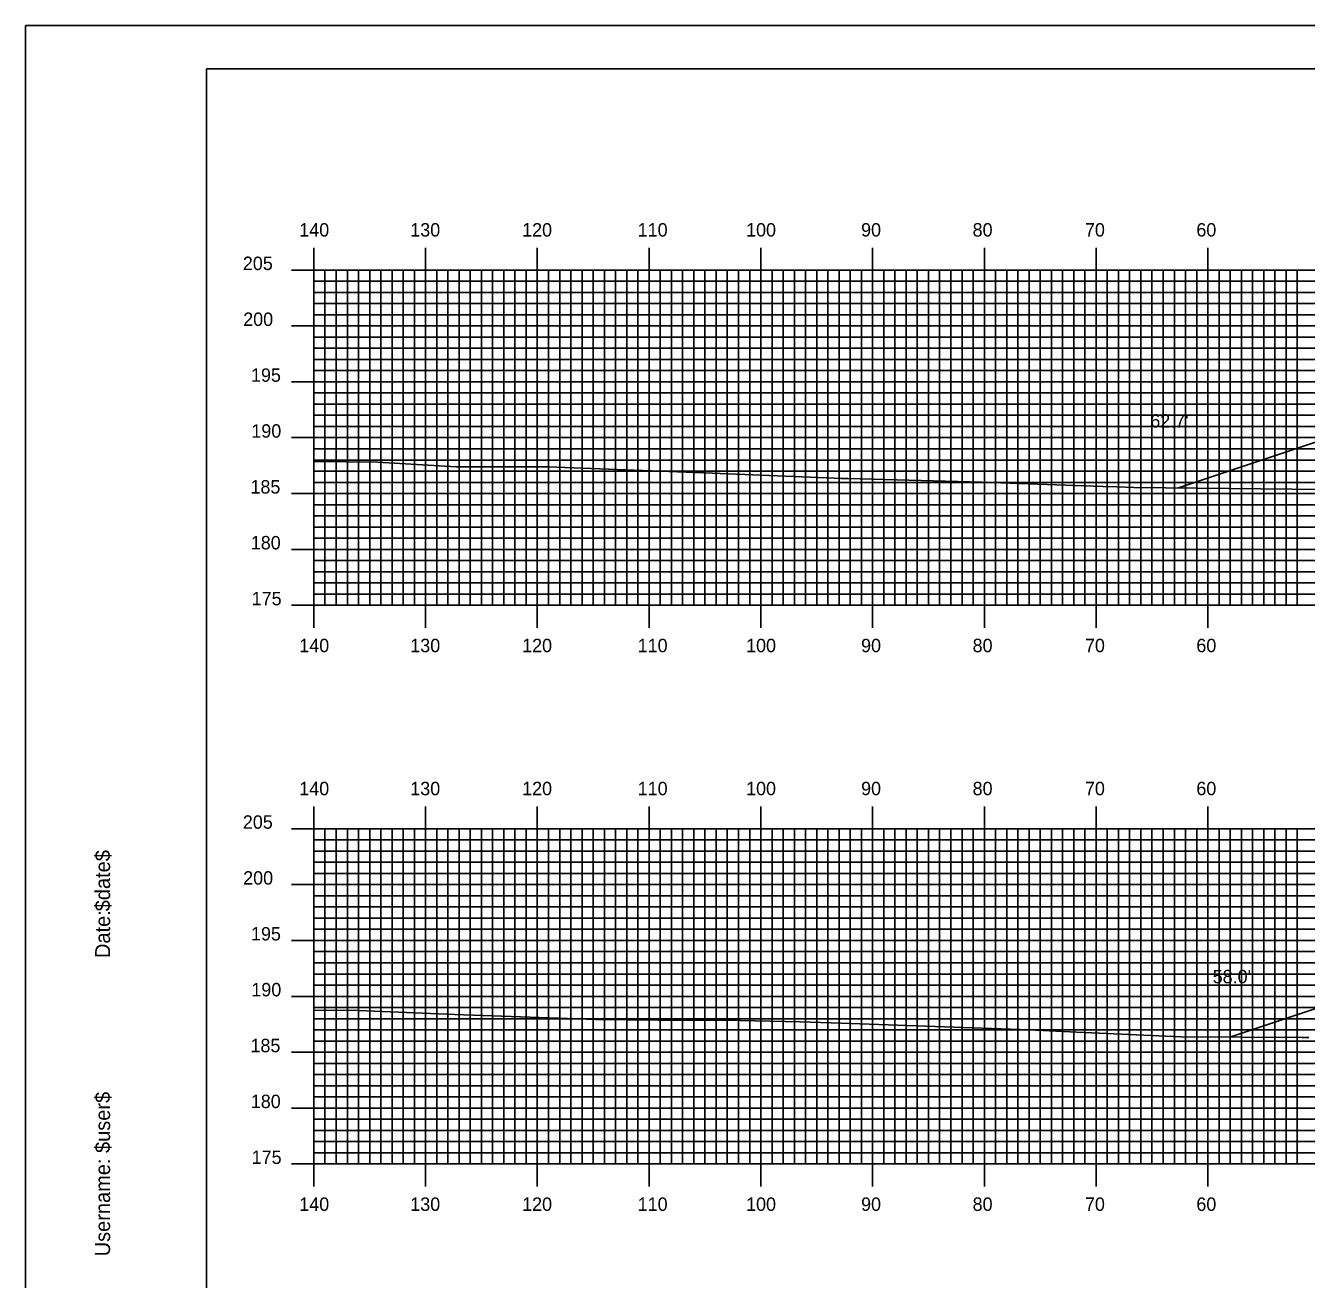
# Model space of a CAD drawing. Extents: x 1808226 to 1808569, y 442591 to 442811.
# Drawn here: x 1808225.5 to 1808340.1, y 442698.3 to 442810.5 of the extents above; entities that cross this region are included whole.
import ezdxf

# ---------------------------------------------------------------- set-up
doc = ezdxf.new("R2010")
doc.units = 0
for name, color, linetype in [('BORDER', 7, 'Continuous'), ('D_Roadway_Centerline', 7, 'Continuous'), ('D_Roadway_SlopeLines', 7, 'Continuous'), ('D_Text_Standard', 7, 'Continuous'), ('H_V ANNOTATION', 7, 'Continuous'), ('MAJOR', 7, 'Continuous'), ('MINOR', 7, 'Continuous'), ('PLOT BOUNDARY', 7, 'Continuous'), ('S_Roadway_Centerline', 7, 'Continuous')]:
    doc.layers.add(name, color=color, linetype=linetype)

msp = doc.modelspace()

# ---------------------------------------------------------------- linework, layer by layer
at = {"layer": 'BORDER'}
msp.add_lwpolyline([(1808241.7, 442596.67), (1808561.7, 442596.67), (1808561.7, 442806.67), (1808241.7, 442806.67)], close=True, dxfattribs=at)
at = {"layer": 'D_Roadway_Centerline'}
for points in [[(1808328.57, 442769.16), (1808357.86, 442778.92), (1808359.81, 442779.41), (1808369.86, 442781.92), (1808379.3, 442782.3), (1808391.3, 442782.54), (1808403.3, 442782.3), (1808411.3, 442781.98), (1808414.3, 442781.86), (1808421.57, 442779.44), (1808456.46, 442767.81)], [(1808333.28, 442720.03), (1808359.3, 442728.7), (1808361.12, 442729.16), (1808371.3, 442731.7), (1808379.3, 442732.02), (1808391.3, 442732.26), (1808403.3, 442732.02), (1808411.3, 442731.7), (1808414.3, 442731.58), (1808421.57, 442729.16), (1808455.49, 442717.85)]]:
    msp.add_lwpolyline(points, dxfattribs=at)
at = {"layer": 'D_Roadway_SlopeLines'}
for points in [[(1808369.86, 442781.92), (1808357.86, 442778.92), (1808328.57, 442769.16)], [(1808371.3, 442731.7), (1808359.3, 442728.7), (1808333.28, 442720.03)]]:
    msp.add_lwpolyline(points, dxfattribs=at)
at = {"layer": 'MAJOR'}
for p, q in [((1808251.3, 442790.67), (1808251.3, 442788.67)), ((1808261.3, 442790.67), (1808261.3, 442788.67)), ((1808271.3, 442790.67), (1808271.3, 442788.67)), ((1808281.3, 442790.67), (1808281.3, 442788.67)), ((1808291.3, 442790.67), (1808291.3, 442788.67)), ((1808301.3, 442790.67), (1808301.3, 442788.67)), ((1808311.3, 442790.67), (1808311.3, 442788.67)), ((1808321.3, 442790.67), (1808321.3, 442788.67)), ((1808331.3, 442790.67), (1808331.3, 442788.67)), ((1808249.29, 442788.67), (1808251.3, 442788.67)), ((1808251.3, 442788.67), (1808531.3, 442788.67)), ((1808251.3, 442758.67), (1808251.3, 442788.67)), ((1808251.3, 442758.67), (1808251.3, 442788.67)), ((1808251.3, 442788.67), (1808531.3, 442788.67)), ((1808261.3, 442758.67), (1808261.3, 442788.67)), ((1808271.3, 442758.67), (1808271.3, 442788.67)), ((1808281.3, 442758.67), (1808281.3, 442788.67)), ((1808291.3, 442758.67), (1808291.3, 442788.67)), ((1808301.3, 442758.67), (1808301.3, 442788.67)), ((1808311.3, 442758.67), (1808311.3, 442788.67)), ((1808321.3, 442758.67), (1808321.3, 442788.67)), ((1808331.3, 442758.67), (1808331.3, 442788.67)), ((1808249.29, 442783.67), (1808251.3, 442783.67)), ((1808251.3, 442783.67), (1808531.3, 442783.67)), ((1808249.29, 442778.67), (1808251.3, 442778.67)), ((1808251.3, 442778.67), (1808531.3, 442778.67)), ((1808249.29, 442773.67), (1808251.3, 442773.67)), ((1808251.3, 442773.67), (1808531.3, 442773.67)), ((1808249.29, 442768.67), (1808251.3, 442768.67)), ((1808251.3, 442768.67), (1808531.3, 442768.67)), ((1808249.29, 442763.67), (1808251.3, 442763.67)), ((1808251.3, 442763.67), (1808531.3, 442763.67)), ((1808249.29, 442758.67), (1808251.3, 442758.67)), ((1808251.3, 442758.67), (1808531.3, 442758.67)), ((1808251.3, 442758.67), (1808531.3, 442758.67)), ((1808251.3, 442756.66), (1808251.3, 442758.67)), ((1808261.3, 442756.66), (1808261.3, 442758.67)), ((1808271.3, 442756.66), (1808271.3, 442758.67)), ((1808281.3, 442756.66), (1808281.3, 442758.67)), ((1808291.3, 442756.66), (1808291.3, 442758.67)), ((1808301.3, 442756.66), (1808301.3, 442758.67)), ((1808311.3, 442756.66), (1808311.3, 442758.67)), ((1808321.3, 442756.66), (1808321.3, 442758.67)), ((1808331.3, 442756.66), (1808331.3, 442758.67)), ((1808251.3, 442740.67), (1808251.3, 442738.67)), ((1808261.3, 442740.67), (1808261.3, 442738.67)), ((1808271.3, 442740.67), (1808271.3, 442738.67)), ((1808281.3, 442740.67), (1808281.3, 442738.67)), ((1808291.3, 442740.67), (1808291.3, 442738.67)), ((1808301.3, 442740.67), (1808301.3, 442738.67)), ((1808311.3, 442740.67), (1808311.3, 442738.67)), ((1808321.3, 442740.67), (1808321.3, 442738.67)), ((1808331.3, 442740.67), (1808331.3, 442738.67)), ((1808249.29, 442738.67), (1808251.3, 442738.67)), ((1808251.3, 442738.67), (1808531.3, 442738.67)), ((1808251.3, 442708.67), (1808251.3, 442738.67)), ((1808251.3, 442708.67), (1808251.3, 442738.67)), ((1808251.3, 442738.67), (1808531.3, 442738.67)), ((1808261.3, 442708.67), (1808261.3, 442738.67)), ((1808271.3, 442708.67), (1808271.3, 442738.67)), ((1808281.3, 442708.67), (1808281.3, 442738.67)), ((1808291.3, 442708.67), (1808291.3, 442738.67)), ((1808301.3, 442708.67), (1808301.3, 442738.67)), ((1808311.3, 442708.67), (1808311.3, 442738.67)), ((1808321.3, 442708.67), (1808321.3, 442738.67)), ((1808331.3, 442708.67), (1808331.3, 442738.67)), ((1808249.29, 442733.67), (1808251.3, 442733.67)), ((1808251.3, 442733.67), (1808531.3, 442733.67)), ((1808249.29, 442728.67), (1808251.3, 442728.67)), ((1808251.3, 442728.67), (1808531.3, 442728.67)), ((1808249.29, 442723.67), (1808251.3, 442723.67)), ((1808251.3, 442723.67), (1808531.3, 442723.67)), ((1808249.29, 442718.67), (1808251.3, 442718.67)), ((1808251.3, 442718.67), (1808531.3, 442718.67)), ((1808249.29, 442713.67), (1808251.3, 442713.67)), ((1808251.3, 442713.67), (1808531.3, 442713.67)), ((1808249.29, 442708.67), (1808251.3, 442708.67)), ((1808251.3, 442708.67), (1808531.3, 442708.67)), ((1808251.3, 442708.67), (1808531.3, 442708.67)), ((1808251.3, 442706.66), (1808251.3, 442708.67)), ((1808261.3, 442706.66), (1808261.3, 442708.67)), ((1808271.3, 442706.66), (1808271.3, 442708.67)), ((1808281.3, 442706.66), (1808281.3, 442708.67)), ((1808291.3, 442706.66), (1808291.3, 442708.67)), ((1808301.3, 442706.66), (1808301.3, 442708.67)), ((1808311.3, 442706.66), (1808311.3, 442708.67)), ((1808321.3, 442706.66), (1808321.3, 442708.67)), ((1808331.3, 442706.66), (1808331.3, 442708.67))]:
    msp.add_line(p, q, dxfattribs=at)
at = {"layer": 'MINOR'}
for p, q in [((1808252.3, 442758.67), (1808252.3, 442788.67)), ((1808253.3, 442758.67), (1808253.3, 442788.67)), ((1808254.3, 442758.67), (1808254.3, 442788.67)), ((1808255.3, 442758.67), (1808255.3, 442788.67)), ((1808256.3, 442758.67), (1808256.3, 442788.67)), ((1808257.3, 442758.67), (1808257.3, 442788.67)), ((1808258.3, 442758.67), (1808258.3, 442788.67)), ((1808259.3, 442758.67), (1808259.3, 442788.67)), ((1808260.3, 442758.67), (1808260.3, 442788.67)), ((1808262.3, 442758.67), (1808262.3, 442788.67)), ((1808263.3, 442758.67), (1808263.3, 442788.67)), ((1808264.3, 442758.67), (1808264.3, 442788.67)), ((1808265.3, 442758.67), (1808265.3, 442788.67)), ((1808266.3, 442758.67), (1808266.3, 442788.67)), ((1808267.3, 442758.67), (1808267.3, 442788.67)), ((1808268.3, 442758.67), (1808268.3, 442788.67)), ((1808269.3, 442758.67), (1808269.3, 442788.67)), ((1808270.3, 442758.67), (1808270.3, 442788.67)), ((1808272.3, 442758.67), (1808272.3, 442788.67)), ((1808273.3, 442758.67), (1808273.3, 442788.67)), ((1808274.3, 442758.67), (1808274.3, 442788.67)), ((1808275.3, 442758.67), (1808275.3, 442788.67)), ((1808276.3, 442758.67), (1808276.3, 442788.67)), ((1808277.3, 442758.67), (1808277.3, 442788.67)), ((1808278.3, 442758.67), (1808278.3, 442788.67)), ((1808279.3, 442758.67), (1808279.3, 442788.67)), ((1808280.3, 442758.67), (1808280.3, 442788.67)), ((1808282.3, 442758.67), (1808282.3, 442788.67)), ((1808283.3, 442758.67), (1808283.3, 442788.67)), ((1808284.3, 442758.67), (1808284.3, 442788.67)), ((1808285.3, 442758.67), (1808285.3, 442788.67)), ((1808286.3, 442758.67), (1808286.3, 442788.67)), ((1808287.3, 442758.67), (1808287.3, 442788.67)), ((1808288.3, 442758.67), (1808288.3, 442788.67)), ((1808289.3, 442758.67), (1808289.3, 442788.67)), ((1808290.3, 442758.67), (1808290.3, 442788.67)), ((1808292.3, 442758.67), (1808292.3, 442788.67)), ((1808293.3, 442758.67), (1808293.3, 442788.67)), ((1808294.3, 442758.67), (1808294.3, 442788.67)), ((1808295.3, 442758.67), (1808295.3, 442788.67)), ((1808296.3, 442758.67), (1808296.3, 442788.67)), ((1808297.3, 442758.67), (1808297.3, 442788.67)), ((1808298.3, 442758.67), (1808298.3, 442788.67)), ((1808299.3, 442758.67), (1808299.3, 442788.67)), ((1808300.3, 442758.67), (1808300.3, 442788.67)), ((1808302.3, 442758.67), (1808302.3, 442788.67)), ((1808303.3, 442758.67), (1808303.3, 442788.67)), ((1808304.3, 442758.67), (1808304.3, 442788.67)), ((1808305.3, 442758.67), (1808305.3, 442788.67)), ((1808306.3, 442758.67), (1808306.3, 442788.67)), ((1808307.3, 442758.67), (1808307.3, 442788.67)), ((1808308.3, 442758.67), (1808308.3, 442788.67)), ((1808309.3, 442758.67), (1808309.3, 442788.67)), ((1808310.3, 442758.67), (1808310.3, 442788.67)), ((1808312.3, 442758.67), (1808312.3, 442788.67)), ((1808313.3, 442758.67), (1808313.3, 442788.67)), ((1808314.3, 442758.67), (1808314.3, 442788.67)), ((1808315.3, 442758.67), (1808315.3, 442788.67)), ((1808316.3, 442758.67), (1808316.3, 442788.67)), ((1808317.3, 442758.67), (1808317.3, 442788.67)), ((1808318.3, 442758.67), (1808318.3, 442788.67)), ((1808319.3, 442758.67), (1808319.3, 442788.67)), ((1808320.3, 442758.67), (1808320.3, 442788.67)), ((1808322.3, 442758.67), (1808322.3, 442788.67)), ((1808323.3, 442758.67), (1808323.3, 442788.67)), ((1808324.3, 442758.67), (1808324.3, 442788.67)), ((1808325.3, 442758.67), (1808325.3, 442788.67)), ((1808326.3, 442758.67), (1808326.3, 442788.67)), ((1808327.3, 442758.67), (1808327.3, 442788.67)), ((1808328.3, 442758.67), (1808328.3, 442788.67)), ((1808329.3, 442758.67), (1808329.3, 442788.67)), ((1808330.3, 442758.67), (1808330.3, 442788.67)), ((1808332.3, 442758.67), (1808332.3, 442788.67)), ((1808333.3, 442758.67), (1808333.3, 442788.67)), ((1808334.3, 442758.67), (1808334.3, 442788.67)), ((1808335.3, 442758.67), (1808335.3, 442788.67)), ((1808336.3, 442758.67), (1808336.3, 442788.67)), ((1808337.3, 442758.67), (1808337.3, 442788.67)), ((1808338.3, 442758.67), (1808338.3, 442788.67)), ((1808339.3, 442758.67), (1808339.3, 442788.67)), ((1808251.3, 442787.67), (1808531.3, 442787.67)), ((1808251.3, 442787.67), (1808253.3, 442787.67)), ((1808251.3, 442786.67), (1808531.3, 442786.67)), ((1808251.3, 442786.67), (1808253.3, 442786.67)), ((1808251.3, 442785.67), (1808531.3, 442785.67)), ((1808251.3, 442785.67), (1808253.3, 442785.67)), ((1808251.3, 442784.67), (1808531.3, 442784.67)), ((1808251.3, 442784.67), (1808253.3, 442784.67)), ((1808251.3, 442782.67), (1808531.3, 442782.67)), ((1808251.3, 442782.67), (1808253.3, 442782.67)), ((1808251.3, 442781.67), (1808531.3, 442781.67)), ((1808251.3, 442781.67), (1808253.3, 442781.67)), ((1808251.3, 442780.67), (1808531.3, 442780.67)), ((1808251.3, 442780.67), (1808253.3, 442780.67)), ((1808251.3, 442779.67), (1808531.3, 442779.67)), ((1808251.3, 442779.67), (1808253.3, 442779.67)), ((1808251.3, 442777.67), (1808531.3, 442777.67)), ((1808251.3, 442777.67), (1808253.3, 442777.67)), ((1808251.3, 442776.67), (1808531.3, 442776.67)), ((1808251.3, 442776.67), (1808253.3, 442776.67)), ((1808251.3, 442775.67), (1808531.3, 442775.67)), ((1808251.3, 442775.67), (1808253.3, 442775.67)), ((1808251.3, 442774.67), (1808531.3, 442774.67)), ((1808251.3, 442774.67), (1808253.3, 442774.67)), ((1808251.3, 442772.67), (1808531.3, 442772.67)), ((1808251.3, 442772.67), (1808253.3, 442772.67)), ((1808251.3, 442771.67), (1808531.3, 442771.67)), ((1808251.3, 442771.67), (1808253.3, 442771.67)), ((1808251.3, 442770.67), (1808531.3, 442770.67)), ((1808251.3, 442770.67), (1808253.3, 442770.67)), ((1808251.3, 442769.67), (1808531.3, 442769.67)), ((1808251.3, 442769.67), (1808253.3, 442769.67)), ((1808251.3, 442767.67), (1808531.3, 442767.67)), ((1808251.3, 442767.67), (1808253.3, 442767.67)), ((1808251.3, 442766.67), (1808531.3, 442766.67)), ((1808251.3, 442766.67), (1808253.3, 442766.67)), ((1808251.3, 442765.67), (1808531.3, 442765.67)), ((1808251.3, 442765.67), (1808253.3, 442765.67)), ((1808251.3, 442764.67), (1808531.3, 442764.67)), ((1808251.3, 442764.67), (1808253.3, 442764.67)), ((1808251.3, 442762.67), (1808531.3, 442762.67)), ((1808251.3, 442762.67), (1808253.3, 442762.67)), ((1808251.3, 442761.67), (1808531.3, 442761.67)), ((1808251.3, 442761.67), (1808253.3, 442761.67)), ((1808251.3, 442760.67), (1808531.3, 442760.67)), ((1808251.3, 442760.67), (1808253.3, 442760.67)), ((1808251.3, 442759.67), (1808531.3, 442759.67)), ((1808251.3, 442759.67), (1808253.3, 442759.67)), ((1808252.3, 442708.67), (1808252.3, 442738.67)), ((1808253.3, 442708.67), (1808253.3, 442738.67)), ((1808254.3, 442708.67), (1808254.3, 442738.67)), ((1808255.3, 442708.67), (1808255.3, 442738.67)), ((1808256.3, 442708.67), (1808256.3, 442738.67)), ((1808257.3, 442708.67), (1808257.3, 442738.67)), ((1808258.3, 442708.67), (1808258.3, 442738.67)), ((1808259.3, 442708.67), (1808259.3, 442738.67)), ((1808260.3, 442708.67), (1808260.3, 442738.67)), ((1808262.3, 442708.67), (1808262.3, 442738.67)), ((1808263.3, 442708.67), (1808263.3, 442738.67)), ((1808264.3, 442708.67), (1808264.3, 442738.67)), ((1808265.3, 442708.67), (1808265.3, 442738.67)), ((1808266.3, 442708.67), (1808266.3, 442738.67)), ((1808267.3, 442708.67), (1808267.3, 442738.67)), ((1808268.3, 442708.67), (1808268.3, 442738.67)), ((1808269.3, 442708.67), (1808269.3, 442738.67)), ((1808270.3, 442708.67), (1808270.3, 442738.67)), ((1808272.3, 442708.67), (1808272.3, 442738.67)), ((1808273.3, 442708.67), (1808273.3, 442738.67)), ((1808274.3, 442708.67), (1808274.3, 442738.67)), ((1808275.3, 442708.67), (1808275.3, 442738.67)), ((1808276.3, 442708.67), (1808276.3, 442738.67)), ((1808277.3, 442708.67), (1808277.3, 442738.67)), ((1808278.3, 442708.67), (1808278.3, 442738.67)), ((1808279.3, 442708.67), (1808279.3, 442738.67)), ((1808280.3, 442708.67), (1808280.3, 442738.67)), ((1808282.3, 442708.67), (1808282.3, 442738.67)), ((1808283.3, 442708.67), (1808283.3, 442738.67)), ((1808284.3, 442708.67), (1808284.3, 442738.67)), ((1808285.3, 442708.67), (1808285.3, 442738.67)), ((1808286.3, 442708.67), (1808286.3, 442738.67)), ((1808287.3, 442708.67), (1808287.3, 442738.67)), ((1808288.3, 442708.67), (1808288.3, 442738.67)), ((1808289.3, 442708.67), (1808289.3, 442738.67)), ((1808290.3, 442708.67), (1808290.3, 442738.67)), ((1808292.3, 442708.67), (1808292.3, 442738.67)), ((1808293.3, 442708.67), (1808293.3, 442738.67)), ((1808294.3, 442708.67), (1808294.3, 442738.67)), ((1808295.3, 442708.67), (1808295.3, 442738.67)), ((1808296.3, 442708.67), (1808296.3, 442738.67)), ((1808297.3, 442708.67), (1808297.3, 442738.67)), ((1808298.3, 442708.67), (1808298.3, 442738.67)), ((1808299.3, 442708.67), (1808299.3, 442738.67)), ((1808300.3, 442708.67), (1808300.3, 442738.67)), ((1808302.3, 442708.67), (1808302.3, 442738.67)), ((1808303.3, 442708.67), (1808303.3, 442738.67)), ((1808304.3, 442708.67), (1808304.3, 442738.67)), ((1808305.3, 442708.67), (1808305.3, 442738.67)), ((1808306.3, 442708.67), (1808306.3, 442738.67)), ((1808307.3, 442708.67), (1808307.3, 442738.67)), ((1808308.3, 442708.67), (1808308.3, 442738.67)), ((1808309.3, 442708.67), (1808309.3, 442738.67)), ((1808310.3, 442708.67), (1808310.3, 442738.67)), ((1808312.3, 442708.67), (1808312.3, 442738.67)), ((1808313.3, 442708.67), (1808313.3, 442738.67)), ((1808314.3, 442708.67), (1808314.3, 442738.67)), ((1808315.3, 442708.67), (1808315.3, 442738.67)), ((1808316.3, 442708.67), (1808316.3, 442738.67)), ((1808317.3, 442708.67), (1808317.3, 442738.67)), ((1808318.3, 442708.67), (1808318.3, 442738.67)), ((1808319.3, 442708.67), (1808319.3, 442738.67)), ((1808320.3, 442708.67), (1808320.3, 442738.67)), ((1808322.3, 442708.67), (1808322.3, 442738.67)), ((1808323.3, 442708.67), (1808323.3, 442738.67)), ((1808324.3, 442708.67), (1808324.3, 442738.67)), ((1808325.3, 442708.67), (1808325.3, 442738.67)), ((1808326.3, 442708.67), (1808326.3, 442738.67)), ((1808327.3, 442708.67), (1808327.3, 442738.67)), ((1808328.3, 442708.67), (1808328.3, 442738.67)), ((1808329.3, 442708.67), (1808329.3, 442738.67)), ((1808330.3, 442708.67), (1808330.3, 442738.67)), ((1808332.3, 442708.67), (1808332.3, 442738.67)), ((1808333.3, 442708.67), (1808333.3, 442738.67)), ((1808334.3, 442708.67), (1808334.3, 442738.67)), ((1808335.3, 442708.67), (1808335.3, 442738.67)), ((1808336.3, 442708.67), (1808336.3, 442738.67)), ((1808337.3, 442708.67), (1808337.3, 442738.67)), ((1808338.3, 442708.67), (1808338.3, 442738.67)), ((1808339.3, 442708.67), (1808339.3, 442738.67)), ((1808251.3, 442737.67), (1808531.3, 442737.67)), ((1808251.3, 442737.67), (1808253.3, 442737.67)), ((1808251.3, 442736.67), (1808531.3, 442736.67)), ((1808251.3, 442736.67), (1808253.3, 442736.67)), ((1808251.3, 442735.67), (1808531.3, 442735.67)), ((1808251.3, 442735.67), (1808253.3, 442735.67)), ((1808251.3, 442734.67), (1808531.3, 442734.67)), ((1808251.3, 442734.67), (1808253.3, 442734.67)), ((1808251.3, 442732.67), (1808531.3, 442732.67)), ((1808251.3, 442732.67), (1808253.3, 442732.67)), ((1808251.3, 442731.67), (1808531.3, 442731.67)), ((1808251.3, 442731.67), (1808253.3, 442731.67)), ((1808251.3, 442730.67), (1808531.3, 442730.67)), ((1808251.3, 442730.67), (1808253.3, 442730.67)), ((1808251.3, 442729.67), (1808531.3, 442729.67)), ((1808251.3, 442729.67), (1808253.3, 442729.67)), ((1808251.3, 442727.67), (1808531.3, 442727.67)), ((1808251.3, 442727.67), (1808253.3, 442727.67)), ((1808251.3, 442726.67), (1808531.3, 442726.67)), ((1808251.3, 442726.67), (1808253.3, 442726.67)), ((1808251.3, 442725.67), (1808531.3, 442725.67)), ((1808251.3, 442725.67), (1808253.3, 442725.67)), ((1808251.3, 442724.67), (1808531.3, 442724.67)), ((1808251.3, 442724.67), (1808253.3, 442724.67)), ((1808251.3, 442722.67), (1808531.3, 442722.67)), ((1808251.3, 442722.67), (1808253.3, 442722.67)), ((1808251.3, 442721.67), (1808531.3, 442721.67)), ((1808251.3, 442721.67), (1808253.3, 442721.67)), ((1808251.3, 442720.67), (1808531.3, 442720.67)), ((1808251.3, 442720.67), (1808253.3, 442720.67)), ((1808251.3, 442719.67), (1808531.3, 442719.67)), ((1808251.3, 442719.67), (1808253.3, 442719.67)), ((1808251.3, 442717.67), (1808531.3, 442717.67)), ((1808251.3, 442717.67), (1808253.3, 442717.67)), ((1808251.3, 442716.67), (1808531.3, 442716.67)), ((1808251.3, 442716.67), (1808253.3, 442716.67)), ((1808251.3, 442715.67), (1808531.3, 442715.67)), ((1808251.3, 442715.67), (1808253.3, 442715.67)), ((1808251.3, 442714.67), (1808531.3, 442714.67)), ((1808251.3, 442714.67), (1808253.3, 442714.67)), ((1808251.3, 442712.67), (1808531.3, 442712.67)), ((1808251.3, 442712.67), (1808253.3, 442712.67)), ((1808251.3, 442711.67), (1808531.3, 442711.67)), ((1808251.3, 442711.67), (1808253.3, 442711.67)), ((1808251.3, 442710.67), (1808531.3, 442710.67)), ((1808251.3, 442710.67), (1808253.3, 442710.67)), ((1808251.3, 442709.67), (1808531.3, 442709.67)), ((1808251.3, 442709.67), (1808253.3, 442709.67))]:
    msp.add_line(p, q, dxfattribs=at)
at = {"layer": 'PLOT BOUNDARY'}
msp.add_lwpolyline([(1808225.51, 442590.55), (1808565.51, 442590.55), (1808565.51, 442810.55), (1808225.51, 442810.55)], close=True, dxfattribs=at)
at = {"layer": 'S_Roadway_Centerline'}
for points in [[(1808251.3, 442771.54), (1808257, 442771.47), (1808264.05, 442771.07), (1808272.24, 442771.07), (1808286.93, 442770.5), (1808297.89, 442770.04), (1808298.5, 442770.03), (1808299.07, 442770.02), (1808311.1, 442769.69), (1808321.91, 442769.29), (1808323.14, 442769.26), (1808324.68, 442769.2), (1808341.69, 442769.04)], [(1808251.3, 442722.44), (1808255.3, 442722.39), (1808263.9, 442722.06), (1808276.54, 442721.61), (1808282.1, 442721.53), (1808289.45, 442721.51), (1808294.81, 442721.4), (1808298.5, 442721.28), (1808315.3, 442720.68), (1808319.57, 442720.47), (1808328.88, 442720.05), (1808339.72, 442720), (1808340.32, 442720)]]:
    msp.add_lwpolyline(points, dxfattribs=at)

# ---------------------------------------------------------------- texts
at = {"layer": 'BORDER'}
for s, p in [('$date$', (1808233.07, 442731.28)), ('Date:', (1808233.07, 442727.1)), ('$user$', (1808233.07, 442709.65)), ('Username:', (1808233.07, 442700.4))]:
    msp.add_text(s, height=1.339, rotation=90, dxfattribs=at).set_placement(p)
at = {"layer": 'D_Text_Standard'}
for s, p in [("62.7'", (1808326.15, 442774.57)), ("58.0'", (1808331.73, 442724.84))]:
    msp.add_text(s, height=1.2, dxfattribs=at).set_placement(p)
at = {"layer": 'H_V ANNOTATION'}
for s, p in [('140', (1808250, 442791.67)), ('130', (1808259.93, 442791.67)), ('120', (1808269.94, 442791.67)), ('110', (1808280.28, 442791.67)), ('100', (1808289.98, 442791.67)), ('90', (1808300.27, 442791.67)), ('80', (1808310.25, 442791.67)), ('70', (1808320.3, 442791.67)), ('60', (1808330.27, 442791.67)), ('205', (1808244.95, 442788.67)), ('200', (1808244.98, 442783.67)), ('195', (1808245.68, 442778.67)), ('190', (1808245.71, 442773.67)), ('185', (1808245.63, 442768.67)), ('180', (1808245.66, 442763.67)), ('175', (1808245.74, 442758.67)), ('140', (1808250, 442754.47)), ('130', (1808259.93, 442754.47)), ('120', (1808269.94, 442754.47)), ('110', (1808280.28, 442754.47)), ('100', (1808289.98, 442754.47)), ('90', (1808300.27, 442754.47)), ('80', (1808310.25, 442754.47)), ('70', (1808320.3, 442754.47)), ('60', (1808330.27, 442754.47)), ('140', (1808250, 442741.67)), ('130', (1808259.93, 442741.67)), ('120', (1808269.94, 442741.67)), ('110', (1808280.28, 442741.67)), ('100', (1808289.98, 442741.67)), ('90', (1808300.27, 442741.67)), ('80', (1808310.25, 442741.67)), ('70', (1808320.3, 442741.67)), ('60', (1808330.27, 442741.67)), ('205', (1808244.95, 442738.67)), ('200', (1808244.98, 442733.67)), ('195', (1808245.68, 442728.67)), ('190', (1808245.71, 442723.67)), ('185', (1808245.63, 442718.67)), ('180', (1808245.66, 442713.67)), ('175', (1808245.74, 442708.67)), ('140', (1808250, 442704.47)), ('130', (1808259.93, 442704.47)), ('120', (1808269.94, 442704.47)), ('110', (1808280.28, 442704.47)), ('100', (1808289.98, 442704.47)), ('90', (1808300.27, 442704.47)), ('80', (1808310.25, 442704.47)), ('70', (1808320.3, 442704.47)), ('60', (1808330.27, 442704.47))]:
    msp.add_text(s, height=1.2, dxfattribs=at).set_placement(p)
at = {"layer": 'MAJOR'}
for p in [(1808251.29, 442758.67), (1808251.29, 442708.67)]:
    msp.add_text('-', height=0.012, dxfattribs=at).set_placement(p)

doc.saveas('drawing.dxf')
